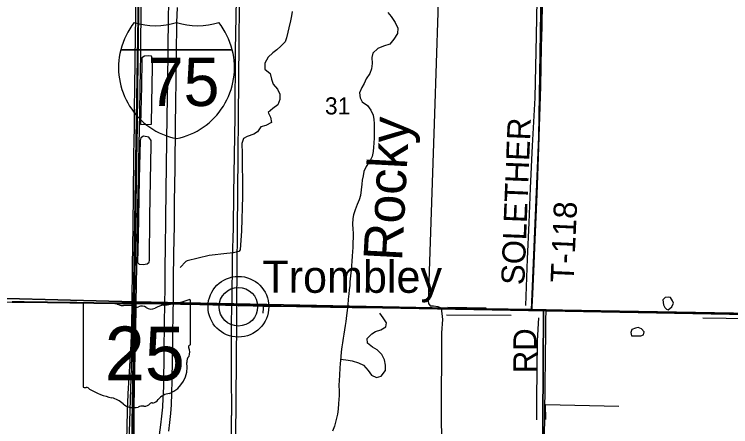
# Model space of a CAD drawing. Extents: x 0 to 39.4, y 0 to 22.
# Drawn here: x 5.077 to 6.833, y 15.083 to 16.092 of the extents above; entities that cross this region are included whole.
import ezdxf

# ---------------------------------------------------------------- set-up
doc = ezdxf.new("R2010")
doc.units = 0
for name, color, linetype in [('GM_X_Interstate_Location', 7, 'Continuous'), ('GM_X_Interstate_Route', 7, 'Continuous'), ('GM_X_Interstate_Shield', 7, 'Continuous'), ('GM_X_Minor_Lake', 7, 'Continuous'), ('GM_X_Minor_River', 7, 'Continuous'), ('GM_X_Minor_River_Text', 7, 'Continuous'), ('GM_X_Rail_Line', 7, 'Continuous'), ('GM_X_Section', 7, 'Continuous'), ('GM_X_Section_Text', 7, 'Continuous'), ('GM_X_State_Location', 7, 'Continuous'), ('GM_X_State_Route', 7, 'Continuous'), ('GM_X_State_Shield', 7, 'Continuous'), ('GM_X_Township_Road', 7, 'Continuous'), ('GM_X_Township_Road_Text', 7, 'Continuous'), ('GM_X_Unincorporated', 7, 'Continuous'), ('GM_X_Unincorporated_Location', 7, 'Continuous'), ('GM_X_Unincorporated_Text', 7, 'Continuous')]:
    doc.layers.add(name, color=color, linetype=linetype)

msp = doc.modelspace()

# ---------------------------------------------------------------- linework, layer by layer
at = {"layer": 'GM_X_Interstate_Route'}
for points in [[(5.0717, 15.3886), (5.1012, 15.3883), (5.1323, 15.3879), (5.1587, 15.3875), (5.1975, 15.3871), (5.2131, 15.3869), (5.2302, 15.3869), (5.2721, 15.386), (5.3234, 15.3852), (5.3425, 15.3852), (5.3658, 15.3852), (5.3704, 15.3852), (5.3782, 15.8208), (5.3836, 16.3856), (5.3867, 16.794), (5.3887, 17.3876)], [(5.3836, 16.3856), (5.3782, 15.8208), (5.3704, 15.3852), (5.3757, 15.3852), (5.3859, 15.3853), (5.4356, 15.3842), (5.446, 15.3839), (5.4669, 15.3839), (5.4843, 15.3835), (5.532, 15.3826), (5.5942, 15.381), (5.6252, 15.3802), (5.6345, 15.38), (5.6625, 15.3792), (5.6867, 15.3789), (5.6998, 15.3787), (5.7309, 15.378), (5.8055, 15.3768), (5.8521, 15.3763), (5.905, 15.3752), (5.9423, 15.3749), (5.9858, 15.3743), (6.1195, 15.3725), (6.1693, 15.372), (6.2345, 15.371), (6.3402, 15.3697), (6.3462, 15.3695), (6.3803, 15.3687), (6.4148, 15.3678), (6.4645, 15.3668), (6.5018, 15.3658), (6.5267, 15.3654), (6.5639, 15.3646), (6.6323, 15.3631), (6.6852, 15.362), (6.7256, 15.3616), (6.7816, 15.3608), (6.8686, 15.3598)], [(5.4328, 15.0628), (5.4365, 15.0874), (5.4391, 15.109), (5.441, 15.1307), (5.4423, 15.1525), (5.4432, 15.1805), (5.4444, 15.2675), (5.4455, 15.3359), (5.4462, 15.3834), (5.4466, 15.4229), (5.4471, 15.4758), (5.4477, 15.5193), (5.4484, 15.5907), (5.4496, 15.6622), (5.4518, 15.8425), (5.4532, 15.9295), (5.4541, 16.0041), (5.4554, 16.0881), (5.4562, 16.116)], [(5.4557, 15.0719), (5.4586, 15.0934), (5.4608, 15.115), (5.4624, 15.1367), (5.4636, 15.1646), (5.4643, 15.1957), (5.4657, 15.2983), (5.4666, 15.3697), (5.4671, 15.3834), (5.4676, 15.4443), (5.4684, 15.5065), (5.4694, 15.5748), (5.47, 15.6339), (5.4713, 15.7147), (5.4724, 15.8235), (5.4733, 15.8732), (5.4748, 15.9944), (5.4758, 16.0721), (5.4768, 16.1095)], [(5.3635, 14.9304), (5.3699, 15.3511), (5.3704, 15.3852), (5.3658, 15.3852), (5.3425, 15.3852), (5.3234, 15.3852), (5.2721, 15.386), (5.2302, 15.3869), (5.2131, 15.3869), (5.1975, 15.3871), (5.1587, 15.3875), (5.1323, 15.3879), (5.1012, 15.3883), (5.0717, 15.3886)], [(6.8686, 15.3598), (6.7816, 15.3608), (6.7256, 15.3616), (6.6852, 15.362), (6.6323, 15.3631), (6.5639, 15.3646), (6.5267, 15.3654), (6.5018, 15.3658), (6.4645, 15.3668), (6.4148, 15.3678), (6.3803, 15.3687), (6.3462, 15.3695), (6.3402, 15.3697), (6.2345, 15.371), (6.1693, 15.372), (6.1195, 15.3725), (5.9858, 15.3743), (5.9423, 15.3749), (5.905, 15.3752), (5.8521, 15.3763), (5.8055, 15.3768), (5.7309, 15.378), (5.6998, 15.3787), (5.6867, 15.3789), (5.6625, 15.3792), (5.6345, 15.38), (5.6252, 15.3802), (5.5942, 15.381), (5.532, 15.3826), (5.4843, 15.3835), (5.4669, 15.3839), (5.446, 15.3839), (5.4356, 15.3842), (5.3859, 15.3853), (5.3757, 15.3852), (5.3704, 15.3852), (5.3699, 15.3511), (5.3635, 14.9304)]]:
    msp.add_lwpolyline(points, dxfattribs=at)
at = {"layer": 'GM_X_Interstate_Shield'}
for p, q in [((5.338, 16.0056), (5.6113, 16.0056)), ((5.6113, 16.0056), (5.338, 16.0056)), ((5.6113, 16.0056), (5.338, 16.0056))]:
    msp.add_line(p, q, dxfattribs=at)
for centre, start, end in [((5.5102, 15.9621), 141.669, 165.8066), ((5.4228, 16.242), 253.0091, 286.9909), ((5.5265, 16.242), 253.0091, 286.9909), ((5.4391, 15.9621), 14.1934, 38.331), ((5.5102, 15.9621), 165.8066, 258.463), ((5.4391, 15.9621), 281.537, 14.1934)]:
    msp.add_arc(centre, 0.1776, start, end, dxfattribs=at)
at = {"layer": 'GM_X_Minor_Lake'}
for p, q in [((5.3887, 15.9154), (5.3865, 15.8228)), ((5.3831, 15.6898), (5.3808, 15.547)), ((6.6006, 15.3052), (6.6127, 15.3056))]:
    msp.add_line(p, q, dxfattribs=at)
for points in [[(5.3865, 15.8228), (5.4135, 15.8234), (5.4144, 15.8751), (5.4162, 15.9636), (5.4162, 15.9826), (5.4136, 15.9898), (5.406, 15.991), (5.3961, 15.9899), (5.3897, 15.9861), (5.3896, 15.9808), (5.3887, 15.9154)], [(5.3808, 15.547), (5.3794, 15.485), (5.3828, 15.4809), (5.3931, 15.4801), (5.4029, 15.4812), (5.4075, 15.4853), (5.4087, 15.4903), (5.409, 15.5985), (5.4129, 15.7721), (5.4122, 15.7835), (5.4069, 15.7915), (5.394, 15.7942), (5.3876, 15.7901), (5.3856, 15.7836), (5.3831, 15.6898)], [(6.6802, 15.3996), (6.6722, 15.3989), (6.6665, 15.3932), (6.6683, 15.3814), (6.6714, 15.3749), (6.6751, 15.3707), (6.6793, 15.3688)], [(6.6793, 15.3688), (6.6883, 15.3764), (6.6925, 15.3851), (6.6904, 15.3913), (6.6855, 15.399), (6.6802, 15.3996)], [(6.6127, 15.3056), (6.6192, 15.3078), (6.6207, 15.315), (6.6143, 15.3223), (6.606, 15.3253), (6.5991, 15.3242), (6.5904, 15.3208), (6.5877, 15.3132), (6.59, 15.3049), (6.6006, 15.3052)]]:
    msp.add_lwpolyline(points, dxfattribs=at)
at = {"layer": 'GM_X_Minor_River'}
for points in [[(5.6416, 18.3738), (5.6397, 18.2519), (5.6368, 17.9388), (5.6359, 17.7474), (5.6326, 17.5373), (5.6301, 17.3295), (5.6288, 17.1521), (5.6277, 17.0461), (5.6263, 16.8296), (5.6266, 16.6901), (5.626, 16.6134), (5.6259, 16.4588), (5.6242, 16.3714), (5.6213, 16.1704), (5.6181, 16.0048), (5.6172, 15.8411), (5.614, 15.6538), (5.6138, 15.5695), (5.6113, 15.4942), (5.6102, 15.3905), (5.6089, 15.3442), (5.6082, 15.2177), (5.6092, 15.1099)], [(6.3964, 17.5457), (6.3973, 17.3656), (6.3956, 17.2984), (6.3922, 17.0541), (6.3894, 16.8623), (6.3882, 16.7111), (6.3859, 16.6063), (6.3821, 16.4558), (6.3784, 16.3601), (6.359, 16.34), (6.3585, 16.171), (6.3562, 16.0407), (6.3531, 15.8883), (6.3459, 15.7702), (6.3414, 15.6665), (6.3377, 15.5822), (6.334, 15.4937), (6.3295, 15.3797)], [(6.1113, 16.8745), (6.1204, 16.8631), (6.1268, 16.8528), (6.1301, 16.833), (6.13, 16.789), (6.1269, 16.645), (6.1222, 16.4562), (6.1179, 16.2974), (6.115, 16.0968), (6.1067, 15.8484), (6.0988, 15.6083), (6.0925, 15.415), (6.0913, 15.3899), (6.092, 15.3842), (6.0966, 15.3789), (6.1042, 15.3788), (6.1152, 15.3773), (6.1231, 15.3739), (6.1264, 15.3454), (6.1241, 15.3123), (6.1236, 15.1012)], [(5.7584, 16.0994), (5.7565, 16.0891), (5.7538, 16.0762), (5.7496, 16.0595), (5.7472, 16.0489), (5.7442, 16.0348), (5.7411, 16.025), (5.7301, 16.0147), (5.7206, 16.0053), (5.7107, 15.9981), (5.6989, 15.9879), (5.6909, 15.9727), (5.6912, 15.9579), (5.7041, 15.9476), (5.7078, 15.9339), (5.7116, 15.9213), (5.7225, 15.9092), (5.7278, 15.8966), (5.7278, 15.8837), (5.7228, 15.8712), (5.7103, 15.8617), (5.6992, 15.8522), (5.7049, 15.8404), (5.7075, 15.8279), (5.6934, 15.8203), (5.6809, 15.8166), (5.6733, 15.8044), (5.6638, 15.7992), (5.6478, 15.7931), (5.6385, 15.7881), (5.6348, 15.776), (5.6351, 15.7679), (5.6352, 15.7597)], [(5.9929, 16.0972), (6.0008, 16.0869), (6.0106, 16.0724), (6.017, 16.0587), (6.0159, 16.0458), (6.0071, 16.0318), (5.9972, 16.0193), (5.982, 16.0144), (5.9679, 16.0091), (5.9554, 15.9974), (5.9531, 15.9864), (5.9542, 15.9723), (5.9526, 15.959), (5.9488, 15.9473), (5.9396, 15.9344), (5.9343, 15.923), (5.929, 15.9131), (5.9232, 15.8998), (5.9251, 15.8877), (5.93, 15.8778), (5.9425, 15.8694), (5.9512, 15.858), (5.9565, 15.8458), (5.9579, 15.8352), (5.959, 15.8253), (5.959, 15.8154), (5.9594, 15.8051), (5.9589, 15.7899), (5.9585, 15.777), (5.9577, 15.7672), (5.9569, 15.7569), (5.9543, 15.7447), (5.9481, 15.733), (5.9394, 15.7201), (5.9337, 15.7072), (5.9317, 15.6966), (5.9298, 15.6863), (5.929, 15.6768), (5.9271, 15.6628), (5.9255, 15.6491), (5.9221, 15.6381), (5.9175, 15.6267), (5.9125, 15.6138), (5.9087, 15.6017), (5.9067, 15.5922), (5.9063, 15.5789), (5.9071, 15.5663), (5.9074, 15.5568), (5.9074, 15.5447), (5.907, 15.5352), (5.9065, 15.5226), (5.9057, 15.5109), (5.905, 15.501), (5.9042, 15.4869), (5.9037, 15.4771), (5.903, 15.4657), (5.901, 15.4524), (5.8998, 15.4376), (5.899, 15.4281), (5.8979, 15.4178), (5.8967, 15.4079), (5.8955, 15.395), (5.8947, 15.3802), (5.8932, 15.3677), (5.8912, 15.3548), (5.8897, 15.3403), (5.8881, 15.3308), (5.8862, 15.3202), (5.8847, 15.3096), (5.8831, 15.2993), (5.8816, 15.2883), (5.88, 15.2784), (5.8785, 15.2663), (5.8777, 15.2541), (5.8757, 15.2367), (5.8753, 15.2268), (5.8737, 15.2089)], [(5.6352, 15.7597), (5.636, 15.6469), (5.6339, 15.5626), (5.6307, 15.5158), (5.6273, 15.5117), (5.6144, 15.5087), (5.5977, 15.5068), (5.5548, 15.502), (5.5005, 15.4889), (5.4978, 15.4874), (5.4834, 15.4722)], [(5.877, 15.2479), (5.8955, 15.2457), (5.9049, 15.2438), (5.9205, 15.2392), (5.9326, 15.2335), (5.9443, 15.2201), (5.9523, 15.2087), (5.9648, 15.203), (5.9765, 15.2067), (5.9868, 15.2204), (5.9865, 15.2337), (5.9842, 15.2462), (5.9778, 15.2595), (5.9665, 15.2714), (5.9551, 15.2778), (5.9426, 15.2874), (5.9415, 15.2988), (5.953, 15.3098), (5.9625, 15.3158), (5.9757, 15.3203), (5.9879, 15.3275), (5.9895, 15.337), (5.9808, 15.3492), (5.9732, 15.3606)], [(6.1398, 15.3757), (6.2339, 15.3739)], [(6.1363, 15.3567), (6.2946, 15.3555)], [(6.3575, 15.0993), (6.3577, 15.1502), (6.3596, 15.293), (6.3624, 15.3496)], [(7.1639, 15.3406), (7.0181, 15.3432), (6.8218, 15.3479), (6.7644, 15.3482)], [(5.8737, 15.2089), (5.8733, 15.1956), (5.8725, 15.1846), (5.8732, 15.1702), (5.8732, 15.1596), (5.8728, 15.1497), (5.872, 15.1398), (5.8708, 15.1261), (5.8693, 15.1136)], [(6.3799, 15.1007), (6.3793, 15.1368), (6.5587, 15.1329)], [(5.6112, 14.8154), (5.6092, 15.1099)], [(5.8693, 15.1136), (5.862, 15.0845), (5.8571, 15.072)], [(6.1236, 15.1012), (6.1254, 14.967), (6.1212, 14.7151), (6.062, 14.7185), (6.0582, 14.6143), (6.0559, 14.5604), (6.0498, 14.4243)]]:
    msp.add_lwpolyline(points, dxfattribs=at)
at = {"layer": 'GM_X_Rail_Line'}
msp.add_line((5.3695, 15.387), (5.6226, 15.3806), dxfattribs=at)
for points in [[(5.3695, 15.387), (5.386, 16.3854), (5.3967, 18.3974), (5.4127, 19.8659), (5.4216, 20.4077), (5.4296, 20.9)], [(5.6115, 14.1), (5.6226, 15.3413), (5.6228, 15.3801), (5.635, 16.7601), (5.6441, 17.4388), (5.6457, 18.044), (5.6539, 18.4301), (5.6611, 19.3588), (5.6728, 20.3992), (5.6755, 20.8483), (5.6758, 20.9)], [(5.368, 14.1), (5.3598, 15.0692), (5.3695, 15.387)], [(5.6226, 15.3806), (5.8907, 15.3757), (7.6341, 15.3434)]]:
    msp.add_lwpolyline(points, dxfattribs=at)
at = {"layer": 'GM_X_Section'}
for points in [[(4.3694, 16.4169), (5.386, 16.3879), (5.3717, 15.3889), (4.3695, 15.415)], [(5.386, 16.3879), (5.8324, 16.3859), (6.3716, 16.3557), (6.3626, 15.7927), (6.3442, 15.3693), (5.3717, 15.3889)], [(6.3716, 16.3557), (7.3732, 16.344), (7.3525, 15.3518), (6.3741, 15.3693), (6.3442, 15.3693), (6.3626, 15.7927)], [(4.3536, 15.4159), (4.3695, 15.415), (5.3717, 15.3889), (5.3657, 14.4352), (4.3571, 14.4954)], [(5.3717, 15.3889), (6.3442, 15.3693), (6.3741, 15.3693), (6.3684, 14.4076), (5.3657, 14.4352)], [(6.3741, 15.3693), (7.3525, 15.3518), (7.3801, 15.3507), (7.3661, 14.4082), (6.3684, 14.4076)]]:
    msp.add_lwpolyline(points, close=True, dxfattribs=at)
at = {"layer": 'GM_X_State_Route'}
msp.add_line((5.3756, 15.3667), (5.376, 15.3847), dxfattribs=at)
for points in [[(5.366, 15.3846), (5.3671, 15.4766), (5.3684, 15.5729), (5.3704, 15.7377), (5.3704, 15.7563), (5.3709, 15.7749), (5.3715, 15.8247), (5.3718, 15.8682), (5.3725, 15.9055), (5.3734, 15.9832), (5.3748, 16.0888), (5.3763, 16.2101)], [(5.376, 15.3847), (5.376, 15.388), (5.3772, 15.4747), (5.3783, 15.5213), (5.3794, 15.5896), (5.3815, 15.6922), (5.3824, 15.7326), (5.3831, 15.773), (5.3849, 15.8507), (5.3857, 15.9129), (5.3864, 15.9533), (5.387, 15.9937), (5.3876, 16.031), (5.388, 16.0869), (5.3882, 16.1833)], [(5.3324, 14.8471), (5.3396, 14.876), (5.3428, 14.8881), (5.3448, 14.8973), (5.3474, 14.9129), (5.3494, 14.9284), (5.3509, 14.9441), (5.3518, 14.9629), (5.3522, 14.9881), (5.3523, 15.013), (5.3547, 15.1199), (5.3563, 15.1636), (5.3611, 15.2446), (5.3635, 15.2852), (5.3654, 15.332), (5.366, 15.3846)], [(5.3638, 14.9299), (5.3648, 14.9356), (5.3666, 14.9479), (5.3676, 14.9602), (5.3683, 14.9788), (5.3691, 15.0348), (5.3719, 15.1779), (5.3733, 15.2619), (5.3756, 15.3667)]]:
    msp.add_lwpolyline(points, dxfattribs=at)
at = {"layer": 'GM_X_State_Shield'}
for p, q in [((5.2456, 15.3822), (5.2456, 15.1821)), ((5.3254, 15.3856), (5.2482, 15.3856)), ((5.5093, 15.2859), (5.5093, 15.3906)), ((5.5092, 15.2859), (5.5093, 15.2859))]:
    msp.add_line(p, q, dxfattribs=at)
for centre, radius, start, end in [((5.2486, 15.3826), 0.00305, 98.1301, 188.1301), ((5.3438, 15.4089), 0.0296, 231.6195, 271.1119), ((5.3536, 15.2733), 0.1064, 80.4867, 94.9883), ((5.3778, 15.3837), 0.00855, 219.7921, 297.1024), ((5.3903, 15.3605), 0.0178, 54.4667, 119.1411), ((5.451, 15.3245), 0.0563, 97.3462, 120.7689), ((5.4153, 15.6585), 0.2796, 275.8445, 288.9065), ((5.5063, 15.391), 0.00294, 351.8621, 97.738), ((5.4132, 15.3922), 0.0214, 233.8562, 294.8282), ((5.5086, 15.2782), 0.00454, 107.944, 210.337), ((5.4797, 15.265), 0.0273, 340.033, 23.6496), ((5.5061, 15.2855), 0.00314, 289.6038, 7.7341), ((5.5198, 15.2421), 0.0198, 136.8065, 186.9296), ((5.431, 15.2288), 0.0699, 292.3089, 8.9858), ((5.2486, 15.1816), 0.00308, 171.9584, 258.3066), ((5.2491, 15.2021), 0.0235, 267.339, 280.6039), ((5.2539, 15.1705), 0.00848, 29.7484, 93.2717), ((5.361, 15.3503), 0.2019, 240.4129, 257.1985), ((5.3008, 15.0922), 0.0632, 47.1842, 75.836), ((5.4605, 15.1259), 0.0383, 94.4031, 142.5768), ((5.3691, 15.1695), 0.0401, 230.7004, 286.2918), ((5.3923, 15.1003), 0.0329, 85.6951, 111.2099), ((5.3952, 15.1545), 0.0214, 268.777, 315.5493), ((5.4145, 15.1352), 0.00601, 65.7517, 132.6484), ((5.412, 15.1627), 0.0226, 282.8732, 323.2771)]:
    msp.add_arc(centre, radius, start, end, dxfattribs=at)
at = {"layer": 'GM_X_Township_Road'}
for p, q in [((5.366, 15.3846), (5.3706, 15.3847)), ((5.3706, 15.3847), (5.376, 15.3847)), ((6.3464, 15.369), (6.3805, 15.3681))]:
    msp.add_line(p, q, dxfattribs=at)
for points in [[(6.3464, 15.369), (6.3466, 15.376), (6.3477, 15.4071), (6.3513, 15.4816), (6.3537, 15.5406), (6.3583, 15.6525), (6.3616, 15.7426), (6.3662, 15.8669), (6.3672, 15.9166), (6.3694, 16.0129), (6.3706, 16.0627), (6.3715, 16.1217), (6.3723, 16.1684), (6.3731, 16.2523), (6.3742, 16.3331), (6.374, 16.3582)], [(4.8735, 15.391), (4.8994, 15.3903), (4.9119, 15.3902), (4.9492, 15.3897), (4.9818, 15.3891), (5.0035, 15.3885), (5.0346, 15.3885), (5.0719, 15.3881), (5.1014, 15.3877), (5.1325, 15.3874), (5.1589, 15.387), (5.1978, 15.3866), (5.2133, 15.3864), (5.2304, 15.3863), (5.2723, 15.3854), (5.3236, 15.3847), (5.3427, 15.3846), (5.366, 15.3846)], [(5.376, 15.3847), (5.3862, 15.3847), (5.4359, 15.3836), (5.4462, 15.3834), (5.4671, 15.3834), (5.4845, 15.383), (5.5322, 15.382), (5.5944, 15.3805), (5.6254, 15.3797), (5.6347, 15.3794), (5.6627, 15.3787), (5.6869, 15.3783)], [(5.6869, 15.3783), (5.6868, 15.373), (5.6866, 15.361)], [(5.6869, 15.3783), (5.7, 15.3781), (5.7311, 15.3775), (5.8057, 15.3763), (5.8524, 15.3757), (5.9052, 15.3747), (5.9425, 15.3744), (5.986, 15.3737), (6.1197, 15.372), (6.1695, 15.3714), (6.2348, 15.3705), (6.3405, 15.3691), (6.3464, 15.369)], [(6.3761, 15.0602), (6.377, 15.1069), (6.3781, 15.1908), (6.3789, 15.2436), (6.3796, 15.3244), (6.3799, 15.3493), (6.3803, 15.3617), (6.3805, 15.3681)], [(6.3805, 15.3681), (6.4151, 15.3672), (6.4648, 15.3662), (6.502, 15.3653), (6.5269, 15.3649), (6.5642, 15.364), (6.6326, 15.3625), (6.6854, 15.3614), (6.7258, 15.3611), (6.7818, 15.3602), (6.8689, 15.3593), (6.884, 15.359)]]:
    msp.add_lwpolyline(points, dxfattribs=at)
at = {"layer": 'GM_X_Unincorporated'}
for radius in [0.0744, 0.0472]:
    msp.add_circle((5.6263, 15.3765), radius, dxfattribs=at)
at = {"layer": 'GM_X_Unincorporated_Location'}
msp.add_line((5.6263, 15.3765), (5.6263, 15.3765), dxfattribs=at)

# ---------------------------------------------------------------- texts
at = {"layer": 'GM_X_Interstate_Location'}
for s in ['-', '.', ',']:
    msp.add_text(s, height=0.000189, dxfattribs=at).set_placement((5.4746, 15.9301))
msp.add_text('75', height=0.000189, rotation=0, dxfattribs=at).set_placement((5.4359, 15.8909))
at = {"layer": 'GM_X_Interstate_Shield'}
msp.add_text('75', height=0.11837, dxfattribs=at).set_placement((5.4039, 15.868))
at = {"layer": 'GM_X_Minor_River_Text'}
msp.add_text('Rocky', height=0.09476, rotation=86.985, dxfattribs=at).set_placement((6.0272, 15.4871))
at = {"layer": 'GM_X_Section_Text'}
msp.add_text('31', height=0.04186, rotation=0, dxfattribs=at).set_placement((5.8384, 15.8473))
at = {"layer": 'GM_X_State_Location'}
msp.add_text('25', height=0.000189, rotation=0, dxfattribs=at).set_placement((5.3268, 15.255))
for s, p in [('s', (5.3745, 15.2688)), ('r', (5.3744, 15.2688))]:
    msp.add_text(s, height=0.000189, dxfattribs=at).set_placement(p)
at = {"layer": 'GM_X_State_Shield'}
msp.add_text('25', height=0.13184, dxfattribs=at).set_placement((5.2989, 15.1962))
at = {"layer": 'GM_X_Township_Road_Text'}
for s, rotation, p in [('SOLETHER', 87.7198, (6.3269, 15.4289)), ('T-118', 87.4731, (6.4478, 15.4348)), ('RD', 90, (6.3569, 15.2139))]:
    msp.add_text(s, height=0.05682, rotation=rotation, dxfattribs=at).set_placement(p)
at = {"layer": 'GM_X_Unincorporated_Text'}
msp.add_text('Trombley', height=0.07898, rotation=0, dxfattribs=at).set_placement((5.6851, 15.4106))

doc.saveas('drawing.dxf')
